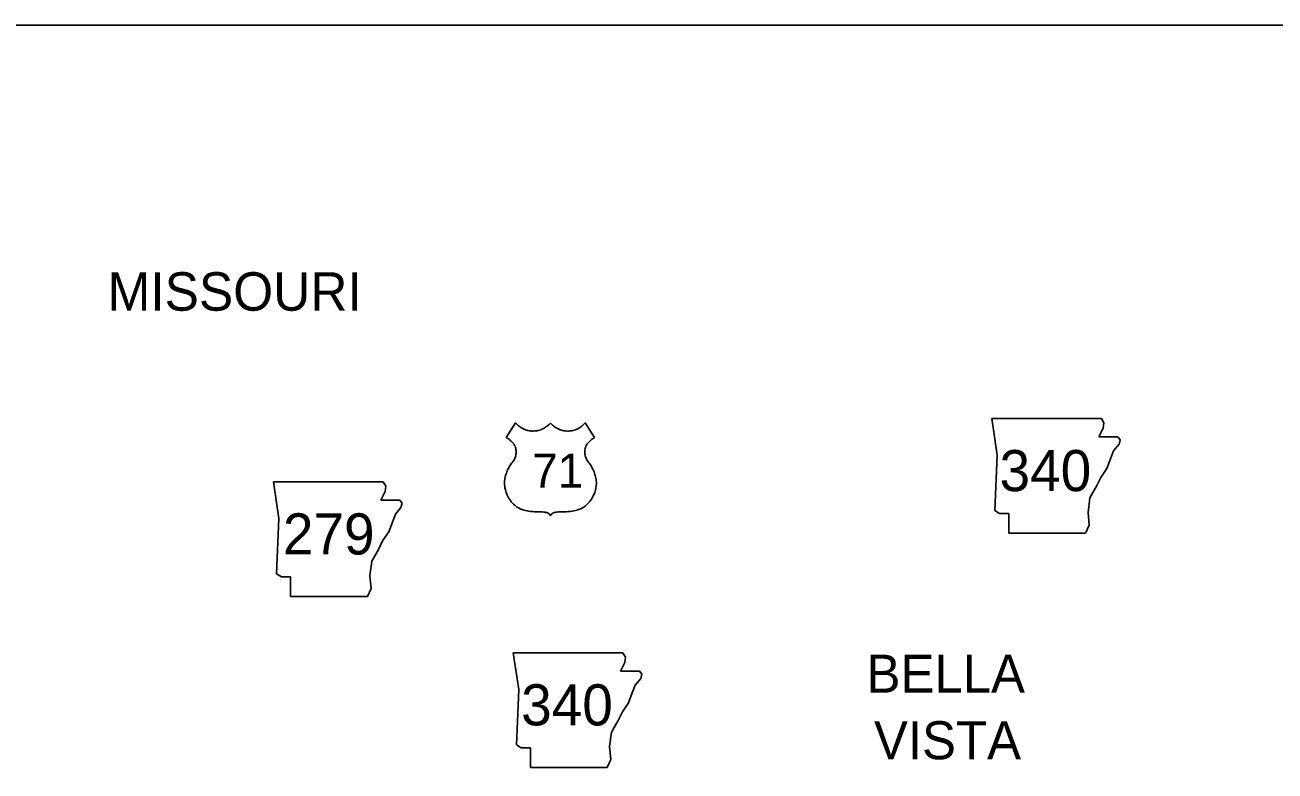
# Model space of a CAD drawing. Extents: x 6028647 to 6035072, y 5366486 to 5368495.
# Drawn here: x 6028934.9 to 6029195, y 5368290.2 to 5368445.5 of the extents above; entities that cross this region are included whole.
import ezdxf

# ---------------------------------------------------------------- set-up
doc = ezdxf.new("R2010")
doc.units = 0
for name, color, linetype in [('21', 7, 'Continuous'), ('22', 7, 'Continuous'), ('25', 7, 'Continuous'), ('R_NoPlot', 7, 'Continuous')]:
    doc.layers.add(name, color=color, linetype=linetype)

msp = doc.modelspace()

# ---------------------------------------------------------------- linework, layer by layer
at = {"layer": '21'}
for p, q in [((6029136.08, 5368363.57), (6029137.22, 5368355.96)), ((6029159.43, 5368362.68), (6029158.9, 5368363.56)), ((6029158.41, 5368359.76), (6029159.3, 5368361.54)), ((6029159.3, 5368361.54), (6029159.43, 5368362.68)), ((6029162.34, 5368359.76), (6029158.41, 5368359.76)), ((6029161.46, 5368356.84), (6029162.6, 5368358.24)), ((6029162.85, 5368359.13), (6029162.34, 5368359.76)), ((6029162.6, 5368358.24), (6029162.85, 5368359.13)), ((6029137.22, 5368355.96), (6029136.71, 5368344.41)), ((6029160.06, 5368353.17), (6029160.82, 5368355.2)), ((6029160.82, 5368355.2), (6029161.46, 5368356.84)), ((6029158.79, 5368351.26), (6029160.06, 5368353.17)), ((6028986.61, 5368350.39), (6028987.75, 5368342.78)), ((6029009.96, 5368349.5), (6029009.43, 5368350.38)), ((6029157.9, 5368349.49), (6029158.79, 5368351.26)), ((6029008.94, 5368346.58), (6029009.83, 5368348.36)), ((6029009.83, 5368348.36), (6029009.96, 5368349.5)), ((6029156.51, 5368347.07), (6029157.9, 5368349.49)), ((6029012.87, 5368346.58), (6029008.94, 5368346.58)), ((6029011.99, 5368343.66), (6029013.13, 5368345.06)), ((6029013.38, 5368345.95), (6029012.87, 5368346.58)), ((6029013.13, 5368345.06), (6029013.38, 5368345.95)), ((6029156.13, 5368344.03), (6029156.51, 5368347.07)), ((6028987.75, 5368342.78), (6028987.24, 5368331.23)), ((6029011.35, 5368342.01), (6029011.99, 5368343.66)), ((6029136.71, 5368344.41), (6029137.73, 5368343.78)), ((6029137.73, 5368343.78), (6029139.63, 5368343.78)), ((6029139.63, 5368343.78), (6029139.63, 5368339.72)), ((6029156.38, 5368341.36), (6029156.13, 5368344.03)), ((6029009.32, 5368338.08), (6029010.59, 5368339.98)), ((6029010.59, 5368339.98), (6029011.35, 5368342.01)), ((6029139.63, 5368339.72), (6029155.62, 5368339.72)), ((6029155.62, 5368339.72), (6029156.38, 5368341.36)), ((6029008.43, 5368336.3), (6029009.32, 5368338.08)), ((6029007.04, 5368333.89), (6029008.43, 5368336.3)), ((6029006.66, 5368330.85), (6029007.04, 5368333.89)), ((6028987.24, 5368331.23), (6028988.26, 5368330.59)), ((6028988.26, 5368330.59), (6028990.16, 5368330.59)), ((6028990.16, 5368330.59), (6028990.16, 5368326.53)), ((6029006.91, 5368328.18), (6029006.66, 5368330.85)), ((6028990.16, 5368326.53), (6029006.15, 5368326.53)), ((6029006.15, 5368326.53), (6029006.91, 5368328.18)), ((6029036.52, 5368314.8), (6029037.66, 5368307.19)), ((6029059.87, 5368313.92), (6029059.34, 5368314.79)), ((6029059.74, 5368312.77), (6029059.87, 5368313.92)), ((6029058.85, 5368311), (6029059.74, 5368312.77)), ((6029062.79, 5368311), (6029058.85, 5368311)), ((6029063.29, 5368310.36), (6029062.79, 5368311)), ((6029061.9, 5368308.08), (6029063.04, 5368309.47)), ((6029063.04, 5368309.47), (6029063.29, 5368310.36)), ((6029037.66, 5368307.19), (6029037.15, 5368295.64)), ((6029060.5, 5368304.4), (6029061.26, 5368306.43)), ((6029061.26, 5368306.43), (6029061.9, 5368308.08)), ((6029059.23, 5368302.5), (6029060.5, 5368304.4)), ((6029056.95, 5368298.31), (6029058.34, 5368300.72)), ((6029058.34, 5368300.72), (6029059.23, 5368302.5)), ((6029056.57, 5368295.26), (6029056.95, 5368298.31)), ((6029037.15, 5368295.64), (6029038.17, 5368295.01)), ((6029056.82, 5368292.6), (6029056.57, 5368295.26)), ((6029038.17, 5368295.01), (6029040.07, 5368295.01)), ((6029040.07, 5368295.01), (6029040.07, 5368290.95)), ((6029040.07, 5368290.95), (6029056.06, 5368290.95)), ((6029056.06, 5368290.95), (6029056.82, 5368292.6))]:
    msp.add_line(p, q, dxfattribs=at)
for points in [[(6029136.08, 5368363.57), (6029158.9, 5368363.56)], [(6028986.61, 5368350.39), (6029009.43, 5368350.38)], [(6029036.52, 5368314.8), (6029059.34, 5368314.79)]]:
    msp.add_lwpolyline(points, dxfattribs=at)
at = {"layer": '22'}
for points in [[(6029044.24, 5368362.63), (6029044.09, 5368362.46), (6029043.95, 5368362.32), (6029043.79, 5368362.16), (6029043.62, 5368362.02), (6029043.45, 5368361.89), (6029043.25, 5368361.74), (6029043.03, 5368361.61), (6029042.78, 5368361.47), (6029042.47, 5368361.33), (6029042.22, 5368361.23), (6029041.95, 5368361.14), (6029041.7, 5368361.08), (6029041.47, 5368361.03), (6029041.23, 5368360.99), (6029041, 5368360.97), (6029040.7, 5368360.96), (6029040.45, 5368360.96), (6029040.23, 5368360.97), (6029040.03, 5368360.99), (6029039.82, 5368361.02), (6029039.55, 5368361.08), (6029039.31, 5368361.14), (6029039.02, 5368361.24), (6029038.76, 5368361.34), (6029038.54, 5368361.44), (6029038.33, 5368361.55), (6029038.14, 5368361.66), (6029037.92, 5368361.81), (6029037.72, 5368361.95), (6029037.55, 5368362.09), (6029037.41, 5368362.22), (6029037.26, 5368362.36), (6029037.12, 5368362.51), (6029037, 5368362.64), (6029035.06, 5368359.63), (6029035.19, 5368359.55), (6029035.36, 5368359.44), (6029035.52, 5368359.33), (6029035.73, 5368359.17), (6029035.89, 5368359.02), (6029036.04, 5368358.88), (6029036.19, 5368358.73), (6029036.35, 5368358.56), (6029036.46, 5368358.43), (6029036.57, 5368358.28), (6029036.68, 5368358.13), (6029036.79, 5368357.97), (6029036.89, 5368357.78), (6029036.96, 5368357.54), (6029037.02, 5368357.31), (6029037.06, 5368357.06), (6029037.08, 5368356.83), (6029037.09, 5368356.61), (6029037.09, 5368356.4), (6029037.07, 5368356.23), (6029037.05, 5368356.02), (6029037.01, 5368355.83), (6029036.95, 5368355.62), (6029036.89, 5368355.44), (6029036.81, 5368355.23), (6029036.69, 5368354.97), (6029036.56, 5368354.76), (6029036.4, 5368354.57), (6029036.21, 5368354.33), (6029036.06, 5368354.11), (6029035.91, 5368353.9), (6029035.78, 5368353.69), (6029035.67, 5368353.5), (6029035.57, 5368353.32), (6029035.46, 5368353.11), (6029035.34, 5368352.87), (6029035.24, 5368352.63), (6029035.16, 5368352.45), (6029035.08, 5368352.22), (6029034.98, 5368351.94), (6029034.91, 5368351.7), (6029034.84, 5368351.45), (6029034.77, 5368351.15), (6029034.73, 5368350.89), (6029034.7, 5368350.62), (6029034.68, 5368350.32), (6029034.68, 5368350.04), (6029034.69, 5368349.76), (6029034.72, 5368349.44), (6029034.77, 5368349.13), (6029034.82, 5368348.9), (6029034.88, 5368348.7), (6029034.94, 5368348.47), (6029035.03, 5368348.18), (6029035.16, 5368347.83), (6029035.27, 5368347.58), (6029035.4, 5368347.32), (6029035.54, 5368347.06), (6029035.73, 5368346.76), (6029035.92, 5368346.49), (6029036.1, 5368346.25), (6029036.31, 5368346.01), (6029036.58, 5368345.73), (6029036.8, 5368345.52), (6029037.04, 5368345.32)], [(6029044.24, 5368362.63), (6029044.39, 5368362.46), (6029044.53, 5368362.32), (6029044.69, 5368362.16), (6029044.87, 5368362.02), (6029045.03, 5368361.89), (6029045.24, 5368361.74), (6029045.45, 5368361.61), (6029045.7, 5368361.47), (6029046.02, 5368361.33), (6029046.26, 5368361.23), (6029046.53, 5368361.14), (6029046.78, 5368361.08), (6029047.01, 5368361.03), (6029047.26, 5368360.99), (6029047.48, 5368360.97), (6029047.79, 5368360.96), (6029048.03, 5368360.96), (6029048.25, 5368360.97), (6029048.46, 5368360.99), (6029048.67, 5368361.02), (6029048.93, 5368361.08), (6029049.17, 5368361.14), (6029049.47, 5368361.24), (6029049.72, 5368361.34), (6029049.95, 5368361.44), (6029050.16, 5368361.55), (6029050.35, 5368361.66), (6029050.56, 5368361.81), (6029050.76, 5368361.95), (6029050.93, 5368362.09), (6029051.07, 5368362.22), (6029051.22, 5368362.36), (6029051.36, 5368362.51), (6029051.48, 5368362.64), (6029053.43, 5368359.63), (6029053.29, 5368359.55), (6029053.12, 5368359.44), (6029052.97, 5368359.33), (6029052.76, 5368359.17), (6029052.59, 5368359.02), (6029052.44, 5368358.88), (6029052.29, 5368358.73), (6029052.14, 5368358.56), (6029052.03, 5368358.43), (6029051.92, 5368358.28), (6029051.81, 5368358.13), (6029051.7, 5368357.97), (6029051.6, 5368357.78), (6029051.52, 5368357.54), (6029051.46, 5368357.31), (6029051.42, 5368357.06), (6029051.4, 5368356.83), (6029051.39, 5368356.61), (6029051.4, 5368356.4), (6029051.41, 5368356.23), (6029051.44, 5368356.02), (6029051.48, 5368355.83), (6029051.53, 5368355.62), (6029051.59, 5368355.44), (6029051.67, 5368355.23), (6029051.8, 5368354.97), (6029051.93, 5368354.76), (6029052.08, 5368354.57), (6029052.27, 5368354.33), (6029052.43, 5368354.11), (6029052.57, 5368353.9), (6029052.7, 5368353.69), (6029052.82, 5368353.5), (6029052.91, 5368353.32), (6029053.02, 5368353.11), (6029053.14, 5368352.87), (6029053.25, 5368352.63), (6029053.32, 5368352.45), (6029053.41, 5368352.22), (6029053.5, 5368351.94), (6029053.58, 5368351.7), (6029053.65, 5368351.45), (6029053.71, 5368351.15), (6029053.75, 5368350.89), (6029053.79, 5368350.62), (6029053.8, 5368350.32), (6029053.81, 5368350.04), (6029053.79, 5368349.76), (6029053.76, 5368349.44), (6029053.71, 5368349.13), (6029053.66, 5368348.9), (6029053.61, 5368348.7), (6029053.54, 5368348.47), (6029053.45, 5368348.18), (6029053.32, 5368347.83), (6029053.21, 5368347.58), (6029053.08, 5368347.32), (6029052.94, 5368347.06), (6029052.76, 5368346.76), (6029052.57, 5368346.49), (6029052.38, 5368346.25), (6029052.18, 5368346.01), (6029051.91, 5368345.73), (6029051.68, 5368345.52), (6029051.44, 5368345.32)], [(6029037.04, 5368345.32), (6029037.28, 5368345.14), (6029037.58, 5368344.95), (6029037.95, 5368344.78), (6029038.38, 5368344.62), (6029038.73, 5368344.5), (6029039.05, 5368344.42), (6029039.4, 5368344.33), (6029039.74, 5368344.27), (6029040.1, 5368344.22), (6029040.56, 5368344.18), (6029040.9, 5368344.17), (6029041.2, 5368344.17), (6029041.49, 5368344.17), (6029041.78, 5368344.16), (6029042.06, 5368344.15), (6029042.3, 5368344.13), (6029042.53, 5368344.11), (6029042.84, 5368344.08), (6029043.13, 5368344.04), (6029043.31, 5368344.02), (6029043.46, 5368343.99), (6029043.63, 5368343.91), (6029043.74, 5368343.86), (6029043.82, 5368343.8), (6029043.95, 5368343.7), (6029044.06, 5368343.58), (6029044.16, 5368343.46), (6029044.24, 5368343.32)], [(6029051.44, 5368345.32), (6029051.2, 5368345.14), (6029050.91, 5368344.95), (6029050.54, 5368344.78), (6029050.11, 5368344.62), (6029049.75, 5368344.5), (6029049.44, 5368344.42), (6029049.08, 5368344.33), (6029048.74, 5368344.27), (6029048.38, 5368344.22), (6029047.93, 5368344.18), (6029047.58, 5368344.17), (6029047.28, 5368344.17), (6029046.99, 5368344.17), (6029046.7, 5368344.16), (6029046.43, 5368344.15), (6029046.19, 5368344.13), (6029045.95, 5368344.11), (6029045.65, 5368344.08), (6029045.35, 5368344.04), (6029045.17, 5368344.02), (6029045.03, 5368343.99), (6029044.85, 5368343.91), (6029044.75, 5368343.86), (6029044.66, 5368343.8), (6029044.54, 5368343.7), (6029044.42, 5368343.58), (6029044.33, 5368343.46), (6029044.24, 5368343.32)]]:
    msp.add_lwpolyline(points, dxfattribs=at)
at = {"layer": 'R_NoPlot'}
msp.add_lwpolyline([(6028702.18, 5368445.48), (6029287.88, 5368445.48), (6029287.88, 5367916.32), (6028702.18, 5367916.32)], close=True, dxfattribs=at)

# ---------------------------------------------------------------- texts
at = {"layer": '21'}
for s, p in [('340', (6029137.71, 5368348.45)), ('279', (6028988.56, 5368335.27)), ('340', (6029038.15, 5368299.69))]:
    msp.add_text(s, height=8.554, dxfattribs=at).set_placement(p)
at = {"layer": '22'}
msp.add_text('71', height=7.128, dxfattribs=at).set_placement((6029040.46, 5368349.15))
at = {"layer": '25'}
for s, height, p in [('MISSOURI', 8, (6028952.07, 5368386.01)), ('BELLA', 7.92, (6029110.04, 5368306.49)), ('VISTA', 7.92, (6029111.58, 5368292.63))]:
    msp.add_text(s, height=height, dxfattribs=at).set_placement(p)

doc.saveas('drawing.dxf')
